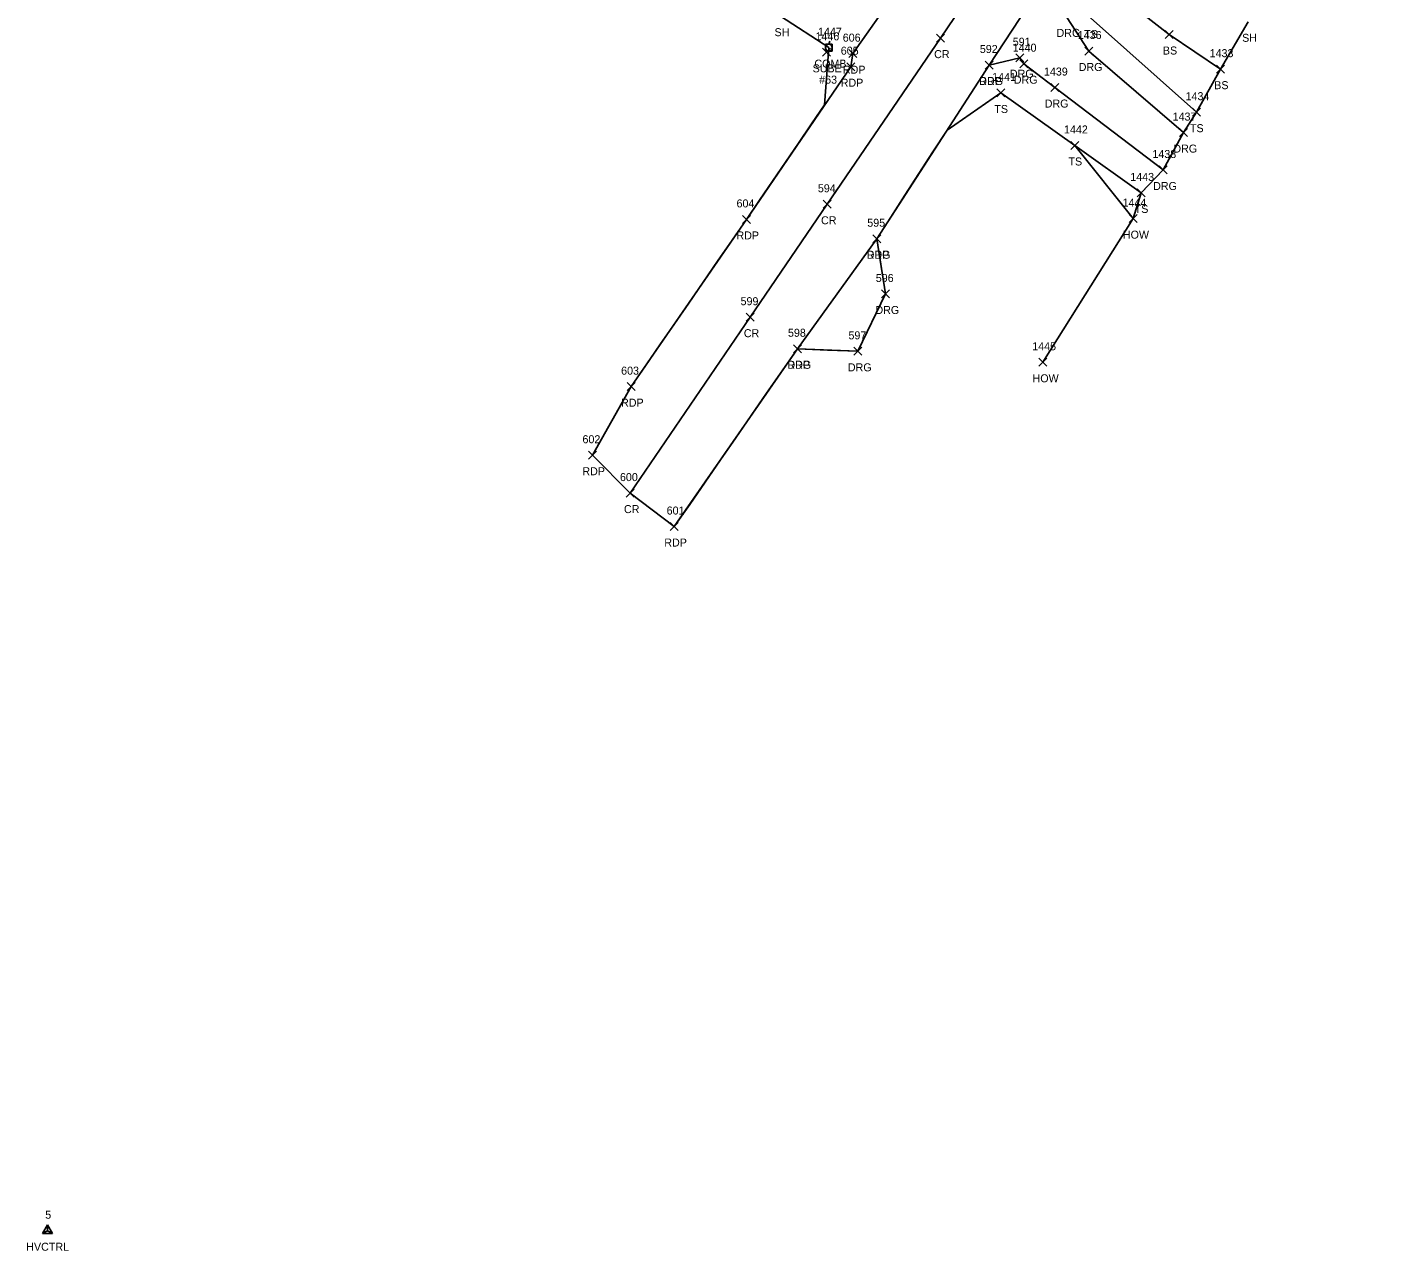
# Model space of a CAD drawing. Extents: x 1639430 to 1640195, y 612006 to 612917.
# Drawn here: x 1639430.3 to 1639769.5, y 612006 to 612311.8 of the extents above; entities that cross this region are included whole.
import ezdxf

# ---------------------------------------------------------------- set-up
doc = ezdxf.new("R2010")
doc.units = 0
for name, color, linetype in [('C_A', 7, 'Continuous'), ('C_I', 7, 'Continuous'), ('CPSM', 7, 'Continuous'), ('L_A', 7, 'Continuous'), ('L_I', 7, 'Continuous'), ('L_TIC', 7, 'Continuous'), ('LBC', 7, 'Continuous'), ('LELB', 7, 'Continuous'), ('LSOGP', 7, 'Continuous'), ('P_A', 7, 'Continuous'), ('P_I', 7, 'Continuous'), ('P_TIC', 7, 'Continuous'), ('PET', 7, 'Continuous'), ('PRC', 7, 'Continuous'), ('R_A', 7, 'Continuous'), ('R_I', 7, 'Continuous'), ('R_TIC', 7, 'Continuous'), ('RDG', 7, 'Continuous'), ('U_A', 7, 'Continuous'), ('U_C', 7, 'Continuous'), ('U_I', 7, 'Continuous'), ('U_TIC', 7, 'Continuous'), ('UP', 7, 'Continuous')]:
    doc.layers.add(name, color=color, linetype=linetype)

msp = doc.modelspace()

# ---------------------------------------------------------------- linework, layer by layer
at = {"layer": 'CPSM'}
for p, q in [((1639434.13, 612010.26), (1639435.38, 612012.42)), ((1639436.63, 612010.26), (1639435.38, 612012.42)), ((1639435.38, 612010.98), (1639435.38, 612012.42)), ((1639434.13, 612010.26), (1639435.38, 612010.98)), ((1639434.13, 612010.26), (1639436.63, 612010.26)), ((1639435.38, 612010.98), (1639435.38, 612010.98)), ((1639435.38, 612010.98), (1639436.63, 612010.26))]:
    msp.add_line(p, q, dxfattribs=at)
at = {"layer": 'L_TIC'}
for points in [[(1639714.77, 612308.95), (1639716.77, 612310.95)], [(1639716.77, 612308.95), (1639714.77, 612310.95)], [(1639727.6, 612300.29), (1639729.6, 612302.29)], [(1639729.6, 612300.29), (1639727.6, 612302.29)], [(1639672.67, 612294.34), (1639674.67, 612296.34)], [(1639674.67, 612294.34), (1639672.67, 612296.34)], [(1639721.58, 612289.54), (1639723.58, 612291.54)], [(1639723.58, 612289.54), (1639721.58, 612291.54)], [(1639691.19, 612281.22), (1639693.19, 612283.22)], [(1639693.19, 612281.22), (1639691.19, 612283.22)], [(1639707.75, 612269.36), (1639709.75, 612271.36)], [(1639709.75, 612269.36), (1639707.75, 612271.36)], [(1639705.82, 612262.93), (1639707.82, 612264.93)], [(1639707.82, 612262.93), (1639705.82, 612264.93)], [(1639683.24, 612227.03), (1639685.24, 612229.03)], [(1639685.24, 612227.03), (1639683.24, 612229.03)]]:
    msp.add_lwpolyline(points, dxfattribs=at)
at = {"layer": 'LBC'}
msp.add_lwpolyline([(1639706.82, 612263.93), (1639684.24, 612228.03)], dxfattribs=at)
at = {"layer": 'LELB'}
for points in [[(1639715.84, 612355.96), (1639700.76, 612333.25), (1639696.04, 612321.16), (1639696.12, 612314.08), (1639722.58, 612290.54)], [(1639769.45, 612328.45), (1639739.98, 612341.85), (1639721.13, 612348.48), (1639710.03, 612334.21), (1639704.22, 612319.02), (1639715.77, 612309.95), (1639728.6, 612301.29)], [(1639673.67, 612295.34), (1639692.19, 612282.22), (1639708.75, 612270.36)]]:
    msp.add_lwpolyline(points, dxfattribs=at)
at = {"layer": 'LSOGP'}
msp.add_lwpolyline([(1639618.65, 612314.53), (1639630.7, 612306.67), (1639629.66, 612292.37), (1639626.41, 612287.6), (1639623.15, 612282.83), (1639619.89, 612278.05), (1639616.63, 612273.28), (1639613.37, 612268.51), (1639610.12, 612263.74), (1639606.51, 612258.52), (1639602.91, 612253.29), (1639599.3, 612248.07), (1639595.69, 612242.84), (1639592.09, 612237.62), (1639588.48, 612232.39), (1639584.88, 612227.17), (1639581.27, 612221.94), (1639576.44, 612213.37), (1639571.61, 612204.8), (1639581.06, 612195.34), (1639592.08, 612186.98), (1639595.93, 612192.53), (1639599.77, 612198.09), (1639603.62, 612203.64), (1639607.47, 612209.19), (1639611.31, 612214.75), (1639615.16, 612220.3), (1639619.01, 612225.86), (1639622.85, 612231.41), (1639630.41, 612231.09), (1639637.97, 612230.77), (1639644.86, 612245.1), (1639643.77, 612252), (1639642.67, 612258.91), (1639646.19, 612264.33), (1639649.71, 612269.76), (1639653.22, 612275.19), (1639656.74, 612280.62), (1639660.26, 612286.05), (1639673.67, 612295.34), (1639692.19, 612282.22), (1639706.82, 612263.93), (1639708.75, 612270.36), (1639714.29, 612276.09), (1639719.34, 612285.44), (1639722.58, 612290.54), (1639728.6, 612301.29), (1639735.53, 612313.13)], dxfattribs=at)
at = {"layer": 'P_TIC'}
for points in [[(1639657.59, 612308.05), (1639659.59, 612310.05)], [(1639659.59, 612308.05), (1639657.59, 612310.05)], [(1639635.18, 612300.91), (1639637.18, 612302.91)], [(1639637.18, 612300.91), (1639635.18, 612302.91)], [(1639635.72, 612304.17), (1639637.72, 612306.17)], [(1639637.72, 612304.17), (1639635.72, 612306.17)], [(1639669.81, 612301.33), (1639671.81, 612303.33)], [(1639671.81, 612301.33), (1639669.81, 612303.33)], [(1639629.32, 612266.52), (1639631.32, 612268.52)], [(1639631.32, 612266.52), (1639629.32, 612268.52)], [(1639609.12, 612262.74), (1639611.12, 612264.74)], [(1639611.12, 612262.74), (1639609.12, 612264.74)], [(1639641.67, 612257.91), (1639643.67, 612259.91)], [(1639643.67, 612257.91), (1639641.67, 612259.91)], [(1639610.01, 612238.3), (1639612.01, 612240.3)], [(1639612.01, 612238.3), (1639610.01, 612240.3)], [(1639621.85, 612230.41), (1639623.85, 612232.41)], [(1639623.85, 612230.41), (1639621.85, 612232.41)], [(1639580.27, 612220.94), (1639582.27, 612222.94)], [(1639582.27, 612220.94), (1639580.27, 612222.94)], [(1639570.61, 612203.8), (1639572.61, 612205.8)], [(1639572.61, 612203.8), (1639570.61, 612205.8)], [(1639580.06, 612194.34), (1639582.06, 612196.34)], [(1639582.06, 612194.34), (1639580.06, 612196.34)], [(1639591.08, 612185.98), (1639593.08, 612187.98)], [(1639593.08, 612185.98), (1639591.08, 612187.98)]]:
    msp.add_lwpolyline(points, dxfattribs=at)
at = {"layer": 'PET'}
for points in [[(1639571.61, 612204.8), (1639581.27, 612221.94), (1639610.12, 612263.74), (1639636.18, 612301.91), (1639636.72, 612305.17), (1639674.04, 612358.08), (1639681.53, 612370.21), (1639706.2, 612406.33), (1639726.2, 612437.98), (1639749.36, 612475.33)], [(1639757.28, 612435.5), (1639729.28, 612391.52), (1639701.75, 612349.14), (1639688.21, 612328.85), (1639670.81, 612302.33), (1639642.67, 612258.91), (1639622.85, 612231.41), (1639592.08, 612186.98)]]:
    msp.add_lwpolyline(points, dxfattribs=at)
at = {"layer": 'PRC'}
msp.add_lwpolyline([(1639744.51, 612441.45), (1639719.17, 612400.96), (1639690.59, 612356.39), (1639658.59, 612309.05), (1639630.32, 612267.52), (1639611.01, 612239.3), (1639581.06, 612195.34)], dxfattribs=at)
at = {"layer": 'R_TIC'}
for points in [[(1639694.68, 612304.83), (1639696.68, 612306.83)], [(1639696.68, 612304.83), (1639694.68, 612306.83)], [(1639669.81, 612301.33), (1639671.81, 612303.33)], [(1639671.81, 612301.33), (1639669.81, 612303.33)], [(1639677.48, 612303.15), (1639679.48, 612305.15)], [(1639679.48, 612303.15), (1639677.48, 612305.15)], [(1639678.45, 612301.66), (1639680.45, 612303.66)], [(1639680.45, 612301.66), (1639678.45, 612303.66)], [(1639686.18, 612295.7), (1639688.18, 612297.7)], [(1639688.18, 612295.7), (1639686.18, 612297.7)], [(1639718.34, 612284.44), (1639720.34, 612286.44)], [(1639720.34, 612284.44), (1639718.34, 612286.44)], [(1639713.29, 612275.09), (1639715.29, 612277.09)], [(1639715.29, 612275.09), (1639713.29, 612277.09)], [(1639641.67, 612257.91), (1639643.67, 612259.91)], [(1639643.67, 612257.91), (1639641.67, 612259.91)], [(1639643.86, 612244.1), (1639645.86, 612246.1)], [(1639645.86, 612244.1), (1639643.86, 612246.1)], [(1639621.85, 612230.41), (1639623.85, 612232.41)], [(1639623.85, 612230.41), (1639621.85, 612232.41)], [(1639636.97, 612229.77), (1639638.97, 612231.77)], [(1639638.97, 612229.77), (1639636.97, 612231.77)]]:
    msp.add_lwpolyline(points, dxfattribs=at)
at = {"layer": 'RDG'}
for points in [[(1639690.13, 612314.36), (1639695.68, 612305.83), (1639719.34, 612285.44)], [(1639678.48, 612304.15), (1639670.81, 612302.33)], [(1639678.48, 612304.15), (1639679.45, 612302.66)], [(1639714.29, 612276.09), (1639687.18, 612296.7), (1639679.45, 612302.66)], [(1639642.67, 612258.91), (1639644.86, 612245.1)], [(1639637.97, 612230.77), (1639622.85, 612231.41)]]:
    msp.add_lwpolyline(points, dxfattribs=at)
at = {"layer": 'U_TIC'}
for points in [[(1639629.12, 612304.5), (1639631.12, 612306.5)], [(1639631.12, 612304.5), (1639629.12, 612306.5)]]:
    msp.add_lwpolyline(points, dxfattribs=at)
at = {"layer": 'UP'}
for p, q in [((1639629.87, 612305.83), (1639629.87, 612307.5)), ((1639629.87, 612307.5), (1639631.53, 612307.5)), ((1639630.95, 612308.33), (1639630.7, 612307.5)), ((1639630.7, 612306.67), (1639630.7, 612306.67)), ((1639631.53, 612307.5), (1639631.53, 612305.83)), ((1639631.53, 612305.83), (1639629.87, 612305.83)), ((1639630.45, 612305), (1639630.7, 612305.83))]:
    msp.add_line(p, q, dxfattribs=at)
msp.add_circle((1639630.7, 612306.67), 0.833, dxfattribs=at)

# ---------------------------------------------------------------- texts
at = {"layer": 'C_A'}
msp.add_text('HVCTRL', height=2, dxfattribs=at).set_placement((1639430.07, 612005.98))
at = {"layer": 'C_I'}
msp.add_text('5', height=2, dxfattribs=at).set_placement((1639434.81, 612013.98))
at = {"layer": 'L_A'}
for s, p in [('SH', (1639617.13, 612309.53)), ('TS', (1639694.53, 612309.08)), ('SH', (1639734.02, 612308.13)), ('BS', (1639714.21, 612304.95)), ('BS', (1639727.04, 612296.29)), ('TS', (1639672.08, 612290.34)), ('TS', (1639720.98, 612285.54)), ('TS', (1639690.6, 612277.22)), ('TS', (1639707.16, 612265.36)), ('HOW', (1639704.21, 612258.93)), ('HOW', (1639681.63, 612223.03))]:
    msp.add_text(s, height=2, dxfattribs=at).set_placement(p)
at = {"layer": 'L_I'}
for s, p in [('1433', (1639725.9, 612304.29)), ('1441', (1639671.54, 612298.34)), ('1434', (1639719.88, 612293.54)), ('1442', (1639689.49, 612285.22)), ('1443', (1639706.06, 612273.36)), ('1444', (1639704.13, 612266.93)), ('1445', (1639681.55, 612231.03))]:
    msp.add_text(s, height=2, dxfattribs=at).set_placement(p)
at = {"layer": 'P_A'}
for s, p in [('CR', (1639657.03, 612304.05)), ('RDP', (1639634.21, 612300.17)), ('RDP', (1639633.67, 612296.91)), ('RDP', (1639668.3, 612297.33)), ('CR', (1639628.76, 612262.52)), ('RDP', (1639607.61, 612258.74)), ('RDP', (1639640.16, 612253.91)), ('CR', (1639609.45, 612234.3)), ('RDP', (1639620.34, 612226.41)), ('RDP', (1639578.76, 612216.94)), ('RDP', (1639569.09, 612199.8)), ('CR', (1639579.49, 612190.34)), ('RDP', (1639589.57, 612181.98))]:
    msp.add_text(s, height=2, dxfattribs=at).set_placement(p)
at = {"layer": 'P_I'}
for s, p in [('606', (1639634.18, 612308.17)), ('605', (1639633.69, 612304.91)), ('592', (1639668.45, 612305.33)), ('594', (1639627.96, 612270.52)), ('604', (1639607.63, 612266.74)), ('595', (1639640.31, 612261.91)), ('599', (1639608.64, 612242.3)), ('598', (1639620.49, 612234.41)), ('603', (1639578.78, 612224.94)), ('602', (1639569.12, 612207.8)), ('600', (1639578.49, 612198.34)), ('601', (1639590.16, 612189.98))]:
    msp.add_text(s, height=2, dxfattribs=at).set_placement(p)
at = {"layer": 'R_A'}
for p in [(1639687.62, 612309.36), (1639693.17, 612300.83), (1639675.96, 612299.15), (1639676.94, 612297.66), (1639668.3, 612297.33), (1639684.67, 612291.7), (1639716.83, 612280.44), (1639711.77, 612271.09), (1639640.16, 612253.91), (1639642.35, 612240.1), (1639620.34, 612226.41), (1639635.46, 612225.77)]:
    msp.add_text('DRG', height=2, dxfattribs=at).set_placement(p)
at = {"layer": 'R_I'}
for s, p in [('1436', (1639692.93, 612308.83)), ('592', (1639668.45, 612305.33)), ('591', (1639676.68, 612307.15)), ('1440', (1639676.67, 612305.66)), ('1439', (1639684.48, 612299.7)), ('1437', (1639716.65, 612288.44)), ('1438', (1639711.59, 612279.09)), ('595', (1639640.31, 612261.91)), ('596', (1639642.44, 612248.1)), ('598', (1639620.49, 612234.41)), ('597', (1639635.61, 612233.77))]:
    msp.add_text(s, height=2, dxfattribs=at).set_placement(p)
at = {"layer": 'U_A'}
for s, p in [('COMB', (1639627.09, 612301.67)), ('SUBE', (1639626.65, 612300.5))]:
    msp.add_text(s, height=2, dxfattribs=at).set_placement(p)
at = {"layer": 'U_C'}
msp.add_text('#63', height=2, dxfattribs=at).set_placement((1639628.29, 612297.67))
at = {"layer": 'U_I'}
for s, p in [('1446', (1639627.37, 612308.5)), ('1447', (1639628.01, 612309.67))]:
    msp.add_text(s, height=2, dxfattribs=at).set_placement(p)

doc.saveas('drawing.dxf')
